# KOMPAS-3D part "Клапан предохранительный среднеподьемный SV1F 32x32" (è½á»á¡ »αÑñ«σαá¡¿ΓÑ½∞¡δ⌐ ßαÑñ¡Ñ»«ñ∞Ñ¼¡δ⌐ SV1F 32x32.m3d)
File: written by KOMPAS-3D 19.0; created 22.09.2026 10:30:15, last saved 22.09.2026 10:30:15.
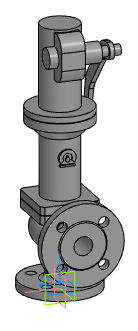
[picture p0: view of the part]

Document properties: Автор: Евгений; Полное имя файла: Z:\3.Личные\sachek\Dendor\_3D для проектировщиков\5.8 SV1F. Клапан предохранительный среднеподьемный\SV1F_STP\Клапан предохранительный среднеподьемный SV1F 32x32.m3d

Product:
- Part/product: Клапан предохранительный среднеподьемный SV1F 32x32
    Масса: 24.7204

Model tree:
1. Операция без истории:1  (labels: Клапан предохранительный среднеподьемный SV1F 32x32)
